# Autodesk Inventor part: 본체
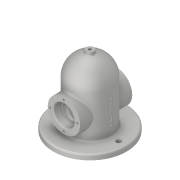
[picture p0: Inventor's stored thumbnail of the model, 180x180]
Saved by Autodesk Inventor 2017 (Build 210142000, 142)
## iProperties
Created: 2019-11
Part Number: 본체
Material: Aluminum 6061
Document SubType Name: Modeling
Designer: 1-08-lg
Density: 2.7 g/cm^3
Appearance: Aluminum - Flat
Mass: 1106.12 g
Surface Area: 883.259 cm^2
Volume: 409.674 cm^3
Author: 1-08-lg
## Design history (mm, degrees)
sketch "Sketch1"
  geometry: C1 r 70 at (0, 0); C2 r 30 at (0, 0); 1 further point
  constraints: 2 centre point, 2 coincident
  dimensions: "d0" = 140 diameter of C1; "d1" = 60 diameter of C2
extrude "Extrusion1" new body sketch "Sketch1" distance "d2" = 10; taper "d3" = 0 deg
sketch "Sketch2"
  geometry: C1 r 40 at (0, 0); C2 r 30 at (0, 0); 1 further point
  constraints: 2 centre point, 2 coincident
  dimensions: "d4" = 80 diameter of C1; "d5" = 60 diameter of C2
extrude "Extrusion2" join sketch "Sketch2" distance "d6" = 80; taper "d7" = 0 deg
workplane "Work Plane2"
sketch "Sketch3"
  geometry: L1 (0, -10)-(0, 40); C1 r 31 at (0, 40)
  constraints: 2 end point, 1 centre point, 1 coincident, 1 vertical
  dimensions: "d9" = 50 distance of L1.start L1.end; "d10" = 62 diameter of C1
extrude "Extrusion3" join sketch "Sketch3" distance "d11" = 100; taper "d12" = 0 deg
sketch "Sketch4"
  geometry: C1 r 20 at (0, 0); 1 further point
  constraints: 1 centre point
  dimensions: "d13" = 40 diameter of C1
extrude "Extrusion4" cut sketch "Sketch4" distance "d14" = 15; taper "d15" = 0 deg
sketch "Sketch5"
  geometry: C1 r 20 at (0, 0); 1 further point
  constraints: 1 centre point
  dimensions: "d16" = 40 diameter of C1
extrude "Extrusion5" cut sketch "Sketch5" distance "d17" = 15; taper "d18" = 0 deg
sketch "Sketch6"
  geometry: C1 r 16.5 at (0, 0); 1 further point
  constraints: 1 centre point
  dimensions: "d19" = 33 diameter of C1
extrude "Extrusion6" cut sketch "Sketch6" distance "d20" = 120.25; taper "d21" = 0 deg
sketch "Sketch7"
  geometry: C1 r 30 at (0, 0); 1 further point
  constraints: 1 centre point, 1 coincident
  dimensions: "d22" = 60 diameter of C1
extrude "Extrusion7" cut sketch "Sketch7" distance "d23" = 120.25; taper "d24" = 0 deg
sketch "Sketch8"
  geometry: L1 (0, 0)-(0, 90); L2 (0, 90)-(40, 90); L3 (-30, 90)-(30, 90) reference; L4 (0, 90)-(0, 130); A1 r 40 centre (0, 90) between (40, 90) and (0, 130)
  constraints: 6 end point, 2 point on circle, 1 centre point, 1 coincident, 1 collinear, 1 vertical
revolve "Revolution1" sketch "Sketch8" stored, may be unused: angle "d27" = 360 deg
sketch "Sketch9"
  geometry: C1 r 7.5 at (0, 0); 1 further point
  constraints: 1 centre point, 1 coincident
  dimensions: "d28" = 15 diameter of C1
extrude "Extrusion8" join sketch "Sketch9" distance "d29" = 135; taper "d30" = 0 deg
sketch "Sketch10"
  geometry: 2 further points
  constraints: 1 coincident
hole "Hole1" sketch "Sketch10" at (0, 0) diameter "d31" = 5.188; stored, may be unused: countersink angle "d35" = 90 deg, drill point angle "d37" = 118 deg; dims "d32" = 12, "d33" = 4, "d34" = 2, "d36" = 16
sketch "Sketch11"
  geometry: C1 r 2.594 at (0, 0) reference; C2 r 30 at (0, 0); 1 further point
  constraints: 1 centre point, 1 coincident
extrude "Extrusion9" cut sketch "Sketch11" distance "d38" = 90; taper "d39" = 0 deg
sketch "Sketch12"
  geometry: L1 (90, 0)-(119, 0); L2 (90, 0)-(90, 30); A1 r 30 centre (90, 0) between (120, 0) and (90, 30); 1 further point
  constraints: 4 end point, 2 point on circle, 1 centre point, 1 point on line
revolve "Revolution2" sketch "Sketch12" stored, may be unused: angle "d42" = 360 deg
sketch "Sketch13" dims "d43" = 52
  geometry: L1 (0, 0)-(0, 26); 2 further points
  constraints: 2 end point, 1 coincident, 1 vertical alignment, 2 other
hole "Hole2" sketch "Sketch13" at (0, 26) diameter "d44" = 3.242; stored, may be unused: countersink angle "d48" = 90 deg, drill point angle "d50" = 118 deg; dims "d45" = 8, "d46" = 4, "d47" = 2, "d49" = 10
pattern_circular "Circular Pattern1" dims angle "d52" = 360 deg
mirror "Mirror1"
sketch "Sketch14"
  geometry: L1 (0, 0)-(55, 0); C1 r 2.594 at (0, 0) reference; C2 r 4.5 at (55, 0); C3 r 4.5 at (-55, 0); A1 r 55 centre (0, 0) between (55, 0) and (-55, 0); 2 further points
  constraints: 3 centre point, 3 coincident, 2 end point, 2 point on circle, 1 horizontal, 1 point on line
  dimensions: "d54" = 110 diameter of A1; "d55" = 9 diameter of C2; "d56" = 9 diameter of C3
extrude "Extrusion10" cut sketch "Sketch14" distance "d57" = 90; taper "d58" = 0 deg
fillet "Fillet1" dims "d59" = 3
chamfer "Chamfer1" distance "d60" = 1; stored, may be unused: second distance "d61" = 2, angle "d62" = 45 deg
workplane "Work Plane4"
sketch "Sketch15"
  geometry: L1 (13.799, 53.178)-(13.799, -53.178); L2 (13.799, -53.178)-(66.861, -53.178); L3 (66.861, -53.178)-(66.861, 53.178); L4 (66.861, 53.178)-(13.799, 53.178); L5 (66.861, 0)-(13.799, 0); L6 (40.33, -53.178)-(40.33, 53.178); L7 (-10, 70)-(-10, -70) reference; 1 further point
  constraints: 4 end point, 4 midpoint, 2 other
  dimensions: "d71" = 50.33 distance between parallel lines of L7 L6
emboss "Emboss1" sketch "Sketch15" dims "d69" = 0.5, "d70" = 0
fillet "Fillet2" dims "d72" = 0.3
fillet "Fillet3" dims "d73" = 0.3
body "Solid1"
other parameters: "d41" = 360 deg
